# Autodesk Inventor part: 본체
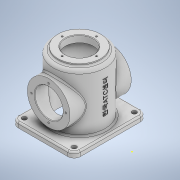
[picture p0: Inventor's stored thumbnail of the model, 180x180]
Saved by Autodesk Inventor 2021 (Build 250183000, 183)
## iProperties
Created: 2021-02
Part Number: 본체
Material: 알루미늄 6061
Document SubType Name: Modeling
Designer: 201-09
Density: 2.7 g/cm^3
Appearance: 기본값
Mass: 1235.48 g
Surface Area: 1067.61 cm^2
Volume: 457.584 cm^3
Author: 201-09
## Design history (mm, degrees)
sketch "스케치1"
  geometry: L1 (60, 70)-(-60, 70); L2 (-60, 70)-(-60, -70); L3 (-60, -70)-(60, -70); L4 (60, -70)-(60, 70); L5 (60, 70)-(-60, -70); L6 (-60, 70)-(60, -70); 1 further point
  constraints: 12 end point, 2 midpoint, 2 parallel, 1 horizontal, 1 perpendicular
  dimensions: "d0" = 120 distance of L3.end L2.end; "d1" = 140 distance between parallel lines of L1 L3
extrude "돌출1" new body sketch "스케치1" distance "d2" = 10; taper "d3" = 0 deg
sketch "스케치2"
  geometry: C1 r 50 at (0, 0); 1 further point
  constraints: 1 centre point, 1 coincident
  dimensions: "d4" = 100 diameter of C1
extrude "돌출2" join sketch "스케치2" distance "d5" = 110; taper "d6" = 0 deg
sketch "스케치3"
  geometry: C1 r 41 at (0, 0); 1 further point
  constraints: 1 centre point, 1 coincident
  dimensions: "d7" = 82 diameter of C1
extrude "돌출3" join sketch "스케치3" distance "d8" = 5; taper "d9" = 0 deg
fillet "모깎기1" dims "d10" = 12
sketch "스케치5"
  geometry: L1 (-48, -70)-(48, -70) reference; L2 (60, -58)-(60, 58) reference; L3 (48, 70)-(-48, 70) reference; L4 (-60, 58)-(-60, -58) reference; C1 r 50 at (0, 0) reference; A1 r 12 centre (-48, -58) between (-60, -58) and (-48, -70) reference; A2 r 12 centre (48, -58) between (48, -70) and (60, -58) reference; A3 r 12 centre (48, 58) between (60, 58) and (48, 70) reference; A4 r 12 centre (-48, 58) between (-48, 70) and (-60, 58) reference; 5 further points
  constraints: 4 coincident
hole "구멍1" sketch "스케치5" at (-48, -58), (-48, 58), (48, 58), (48, -58) diameter "d11" = 9; stored, may be unused: countersink angle "d15" = 90 deg, drill point angle "d17" = 118 deg; dims "d12" = 6, "d13" = 4, "d14" = 2, "d16" = 8
sketch "스케치6"
  geometry: C1 r 27 at (0, 0); 1 further point
  constraints: 1 centre point, 1 coincident
  dimensions: "d18" = 54 diameter of C1
extrude "돌출4" cut sketch "스케치6" distance "d19" = 13; taper "d20" = 0 deg
sketch "스케치7"
  geometry: C1 r 42 at (0, 0); 1 further point
  constraints: 1 centre point, 1 coincident
  dimensions: "d21" = 84 diameter of C1
sketch "스케치8" dims "d24" = 66
  geometry: L1 (-92.25, 0)-(133.5, 0) reference; L2 (0, 98)-(0, -98) reference; C1 r 41 at (0, 0) reference; 6 further points
  constraints: 2 vertical alignment, 1 coincident, 1 point on line, 7 other
  dimensions: "d27" = 360 deg dimension on C1.centre point (0, 33) (derived)
hole "구멍2" sketch "스케치8" at (0, 33), (-33, 0), (0, -33), (33, 0) diameter "d29" = 3.242; stored, may be unused: countersink angle "d33" = 90 deg, drill point angle "d35" = 118 deg; dims "d30" = 8, "d31" = 4, "d32" = 2, "d34" = 10
extrude "돌출8" cut sketch "스케치7" extent not by distance; stored distance "d43" = 0; taper "d44" = 0 deg
node "작업 평면1"
sketch "스케치12"
  geometry: L1 (-48, 0)-(48, 0) reference; C1 r 41 at (0, 60); 2 further points
  constraints: 1 centre point, 1 midpoint, 1 vertical alignment
  dimensions: "d58" = 82 diameter of C1; "d59" = 60 distance from line of L1 C1.centre
extrude "돌출9" join sketch "스케치12" stored distance "d61" = 118; taper "d62" = 0 deg
sketch "스케치13"
  geometry: C1 r 41 at (0, 0) reference; C2 r 27 at (0, 0); 1 further point
  constraints: 1 centre point, 1 coincident
  dimensions: "d63" = 54 diameter of C2
extrude "돌출10" cut sketch "스케치13" extent not by distance; stored distance "d64" = 0; taper "d65" = 0 deg
sketch "스케치14" dims "d66" = 66
  geometry: C1 r 41 at (0, 0) reference; 6 further points
  constraints: 2 vertical alignment, 1 coincident, 7 other
  dimensions: "d69" = 360 deg dimension on C1.centre point (0, 33) (derived)
hole "구멍4" sketch "스케치14" at (0, 33), (-33, 0), (0, -33), (33, 0) diameter "d71" = 3.242; stored, may be unused: countersink angle "d75" = 90 deg, drill point angle "d77" = 118 deg; dims "d72" = 8, "d73" = 4, "d74" = 2, "d76" = 10
node "작업 평면2"
sketch "스케치15"
  geometry: 1 further point
sketch "스케치16"
  geometry: L1 (0, 58)-(0, -58) reference; 2 further points
  constraints: 1 horizontal alignment, 1 other
  dimensions: "d79" = 66 distance from line of L1 point (66, 0)
feature "엠보싱1" sketch "스케치16" dims "d0" = 120, "d1" = 140, "d80" = 0.5, "d81" = 0
fillet "모깎기2" dims "d82" = 3
fillet "모깎기3" dims "d83" = 3
fillet "모깎기4" dims "d84" = 3
fillet "모깎기5" dims "d85" = 6
fillet "모깎기6" dims "d86" = 3
chamfer "모따기1" distance "d87" = 1; stored, may be unused: second distance "d88" = 2, angle "d89" = 45 deg
fillet "모깎기7" dims "d90" = 3
node "솔리드1"
mirror "미러1"
mirror "미러2"
mirror "미러3"
node "투영된 루프1"
feature "A9D066F2-1C7D-4E18-AEED-F7BC21143FA4" dims "d11" = 9, "d12" = 6, "d13" = 4, "d14" = 2, "d15" = 90 deg, "d16" = 8, "d17" = 118 deg
other parameters: "d57" = 59, "d78" = 101.25
